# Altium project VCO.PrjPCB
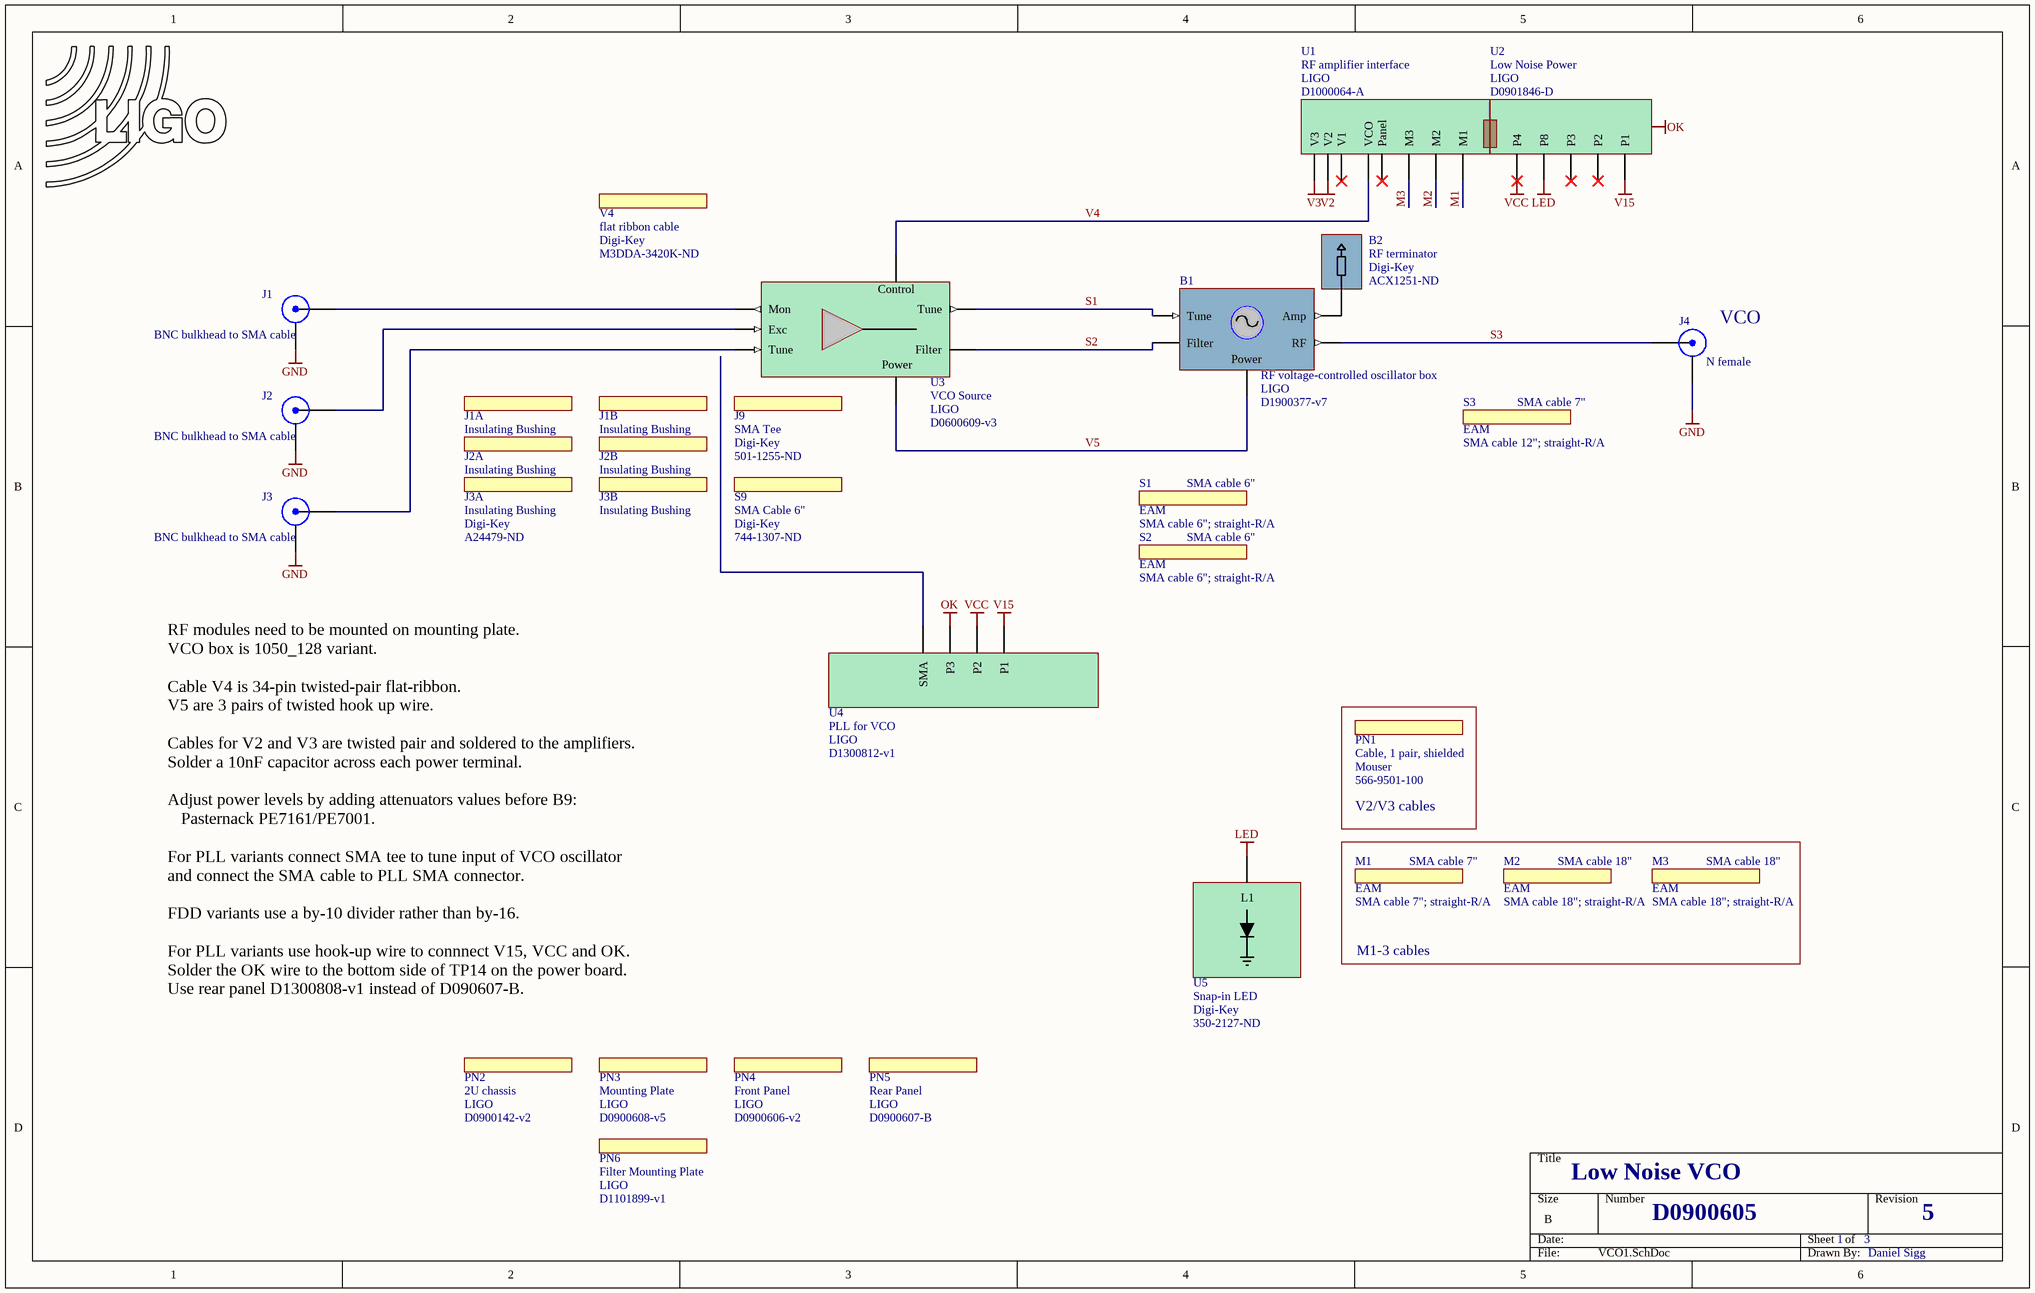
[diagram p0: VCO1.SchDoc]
Title: D0900605
3 sheets, 238 parts. Net scope: global (net labels, ports and power ports of the same name join across sheets).
Sheets:
  VCO1.SchDoc
  VCO2.SchDoc
  VCO3.SchDoc

## Sheet VCO1.SchDoc: D0900605
size B; Engineer: Daniel Sigg; Revision: 5; PageSetup: Record=PageOptions¦CenterHorizontal=True¦CenterVertical=True¦PrintScale=1.12¦XCorrection=1.00¦YCorrection=1.00¦PrintKind=0¦BorderSize=5000000¦LeftOffset=0¦BottomOffset=0¦Orientation=2¦PaperLength=1000¦PaperWidth=1000¦Scale=100¦PaperSource=7¦PrintQuality=-4¦MediaType=1¦DitherType=10¦PaperKind=11 x 17¦PrintScaleMode=1

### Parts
B1  RF voltage-controlled oscillator box  Distributor: LIGO  Part Number: D1900377-v7
B2  RF terminator  Distributor: Digi-Key  Part Number: ACX1251-ND
J1  BNC bulkhead to SMA cable  [BNC1]  (mechanical)
J1A  Insulating Bushing  (mechanical)
J1B  Insulating Bushing  (mechanical)
J2  BNC bulkhead to SMA cable  [BNC1]  (mechanical)
J2A  Insulating Bushing  (mechanical)
J2B  Insulating Bushing  (mechanical)
J3  BNC bulkhead to SMA cable  [BNC1]  (mechanical)
J3A  Insulating Bushing  Part Number: A24479-ND  Distributor: Digi-Key  (mechanical)
J3B  Insulating Bushing  (mechanical)
J4  N female  [BNC1]  (mechanical)
J9  SMA Tee  Part Number: 501-1255-ND  Distributor: Digi-Key  (mechanical)
LOGO1  LIGO logo  [LIGO_LOGO]  (value not drawn)  (no BOM)
M1  SMA cable 7"  Part Number: SMA cable 7"; straight-R/A  Distributor: EAM  (mechanical)
M2  SMA cable 18"  Part Number: SMA cable 18"; straight-R/A  Distributor: EAM  (mechanical)
M3  SMA cable 18"  Part Number: SMA cable 18"; straight-R/A  Distributor: EAM  (mechanical)
PN1  Cable, 1 pair, shielded  Part Number: 566-9501-100  Distributor: Mouser  (mechanical)
PN2  2U chassis  Part Number: D0900142-v2  Distributor: LIGO  (mechanical)
PN3  Mounting Plate  Part Number: D0900608-v5  Distributor: LIGO  (mechanical)
PN4  Front Panel  Part Number: D0900606-v2  Distributor: LIGO  (mechanical)
PN5  Rear Panel  Part Number: D0900607-B  Distributor: LIGO  (mechanical)
PN6  Filter Mounting Plate  Part Number: D1101899-v1  Distributor: LIGO  (mechanical)
S1  SMA cable 6"  Part Number: SMA cable 6"; straight-R/A  Distributor: EAM  (mechanical)
S2  SMA cable 6"  Part Number: SMA cable 6"; straight-R/A  Distributor: EAM  (mechanical)
S3  SMA cable 7"  Part Number: SMA cable 12"; straight-R/A  Distributor: EAM  (mechanical)
S9  SMA Cable 6"  Part Number: 744-1307-ND  Distributor: Digi-Key  (mechanical)
U1  RF amplifier interface  Distributor: LIGO  Part Number: D1000064-A
U2  Low Noise Power  Distributor: LIGO  Part Number: D0901846-D
U3  VCO Source  Distributor: LIGO  Part Number: D0600609-v3
U4  PLL for VCO  Distributor: LIGO  Part Number: D1300812-v1
U5  Snap-in LED  Distributor: Digi-Key  Part Number: 350-2127-ND
V4  flat ribbon cable  Part Number: M3DDA-3420K-ND  Distributor: Digi-Key  (mechanical)

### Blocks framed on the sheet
V2/V3 cables: PN1
M1-3 cables: M1-M3

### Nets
GND: J1.2(Y) J2.2(Y) J3.2(Y) J4.2(Y)
LED: U2.4(P8) U5.1(Panel)
OK: U4.3(P3)
V2: U1.6(V2)
V3: U1.7(V3)
V15: U2.1(P1) U4.1(P1)
VCC: U2.5(P4) U4.2(P2)
M1: U1.1(M1)
M2: U1.2(M2)
M3: U1.3(M3)
S1: B1.4(Tune) U3.2(Tune)
S2: B1.5(Filter) U3.1(Filter)
S3: B1.1(RF) J4.1(X)
V4: U1.8(VCO) U3.3(Power)
V5: B1.2(Power) U3.3(Power)
NetB1_3: B1.3(Amp) B2.1(I)
NetJ1_1: J1.1(X) U3.4(Mon)
NetJ2_1: J2.1(X) U3.5(Exc)
NetJ3_1: J3.1(X) U3.6(Tune)

Not connected (* = marked no-connect by the designer): U1 4(Panel)* 5(V1)*; U2 2(P2)* 3(P3)*; U4 4(SMA)

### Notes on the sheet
- (near J4) VCO
- RF modules need to be mounted on mounting plate.
  VCO box is 1050_128 variant.
  Cable V4 is 34-pin twisted-pair flat-ribbon.
  V5 are 3 pairs of twisted hook up wire.
  Cables for V2 and V3 are twisted pair and soldered to the amplifiers.
  Solder a 10nF capacitor across each power terminal.
  Adjust power levels by adding attenuators values before B9:
  Pasternack PE7161/PE7001.
  For PLL variants connect SMA tee to tune input of VCO oscillator
  and connect the SMA cable to PLL SMA connector.
  FDD variants use a by-10 divider rather than by-16.
  For PLL variants use hook-up wire to connnect V15, VCC and OK.
  Solder the OK wire to the bottom side of TP14 on the power board.
  Use rear panel D1300808-v1 instead of D090607-B.
- Low Noise VCO
- D0900605
- 1
- 3
- 5
- Daniel Sigg
- Labels drawn without touching a wire or pin: OK

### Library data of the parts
B1 = RFVCOBox
B2 = RFTerminator
J1-J3 = BNC: Part Number: PE3681-12
J1A J1B J2A J2B J3B = Partlist: Additional part number; Part Number: A24479-ND
J3A J9 PN1 PN2 PN4 PN5 S9 = Partlist: Additional part number
J4 = BNC: N-to-SMA bulkhead; Part Number: PE9252
LOGO1 = LIGO_logo
M1 S1-S3 = Partlist: Belden 1671A, L=7", SMA-SMA R/A
M2 M3 = Partlist: Belden 1671A, L=18", SMA-SMA R/A
PN3 PN6 = Partlist: panel
U1 = RFAmplifierInterface
U2 = LowNoisePower: Low Noise Power Board
U3 = RFVCOSourceV3: VCO Source V3
U4 = PLL
U5 = RFAmplifierLED: RF amplifier LED
V4 = Partlist

## Sheet VCO2.SchDoc: D0900605
size B; PageSetup: Record=PageOptions¦CenterHorizontal=True¦CenterVertical=True¦PrintScale=1.12¦XCorrection=1.00¦YCorrection=1.00¦PrintKind=0¦BorderSize=5000000¦LeftOffset=0¦BottomOffset=0¦Orientation=2¦PaperLength=1000¦PaperWidth=1000¦Scale=100¦PaperSource=7¦PrintQuality=-4¦MediaType=1¦DitherType=10¦PaperKind=11 x 17¦PrintScaleMode=1
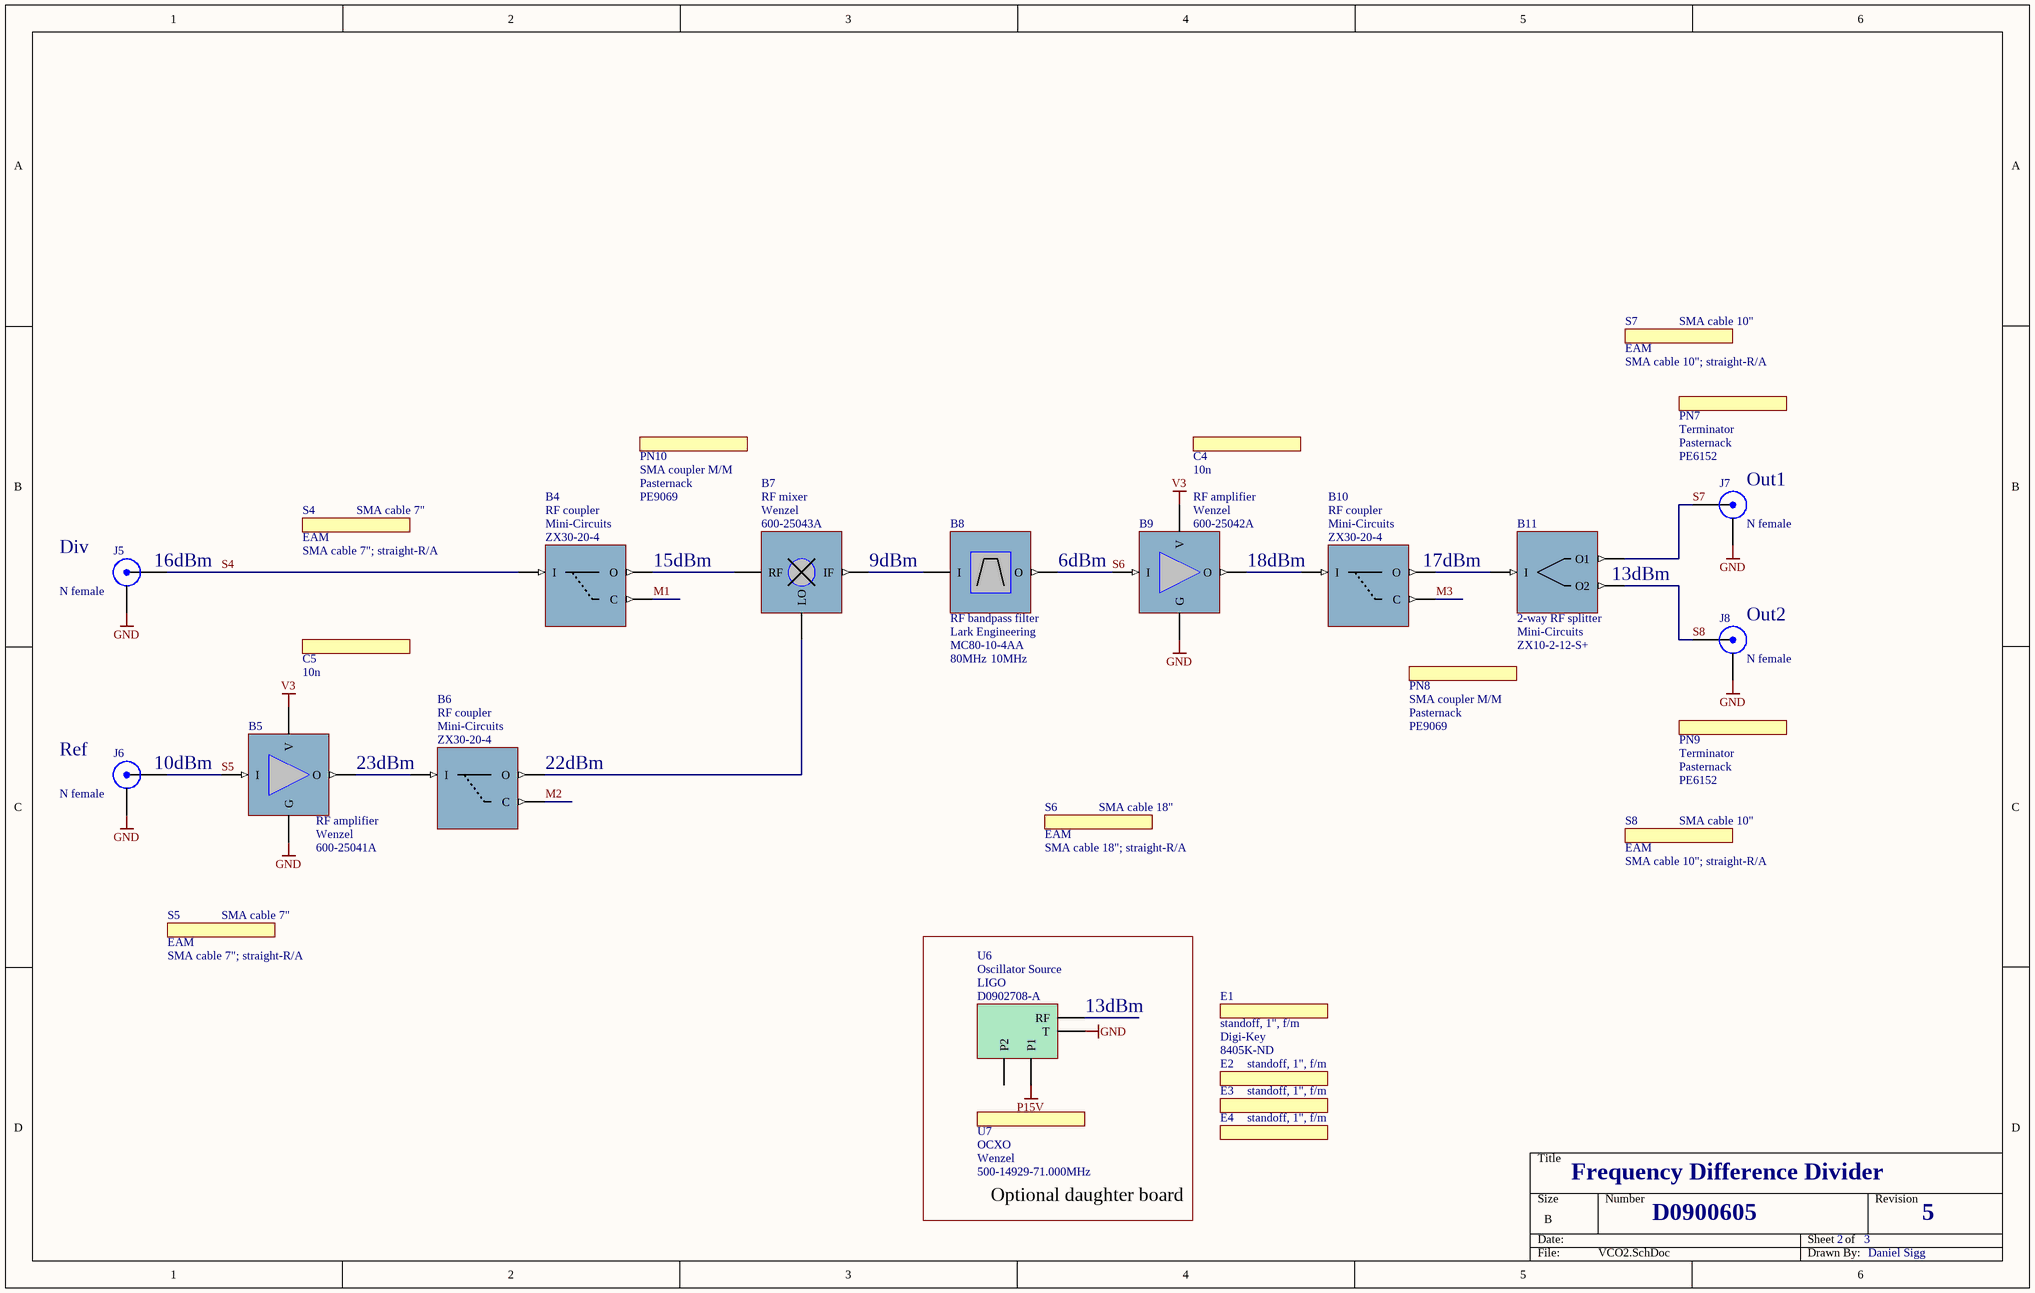
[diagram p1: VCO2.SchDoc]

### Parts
B4  RF coupler  Distributor: Mini-Circuits  Part Number: ZX30-20-4  (mechanical)
B5  RF amplifier  Distributor: Wenzel  Part Number: 600-25041A  (mechanical)
B6  RF coupler  Distributor: Mini-Circuits  Part Number: ZX30-20-4  (mechanical)
B7  RF mixer  Distributor: Wenzel  Part Number: 600-25043A  (mechanical)
B8  RF bandpass filter  Distributor: Lark Engineering  Part Number: MC80-10-4AA  Center Frequency: 80MHz  Width: 10MHz  (mechanical)
B9  RF amplifier  Distributor: Wenzel  Part Number: 600-25042A  (mechanical)
B10  RF coupler  Distributor: Mini-Circuits  Part Number: ZX30-20-4  (mechanical)
B11  2-way RF splitter  Distributor: Mini-Circuits  Part Number: ZX10-2-12-S+  (mechanical)
C4  10n  (mechanical)
C5  10n  (mechanical)
E1  standoff, 1", f/m  Part Number: 8405K-ND  Distributor: Digi-Key  (mechanical)
E2  standoff, 1", f/m  (mechanical)
E3  standoff, 1", f/m  (mechanical)
E4  standoff, 1", f/m  (mechanical)
J5  N female  [BNC1]  (mechanical)
J6  N female  [BNC1]  (mechanical)
J7  N female  [BNC1]  (mechanical)
J8  N female  [BNC1]  (mechanical)
PN7  Terminator  Part Number: PE6152  Distributor: Pasternack  (mechanical)
PN8  SMA coupler M/M  Part Number: PE9069  Distributor: Pasternack  (mechanical)
PN9  Terminator  Part Number: PE6152  Distributor: Pasternack  (mechanical)
PN10  SMA coupler M/M  Part Number: PE9069  Distributor: Pasternack  (mechanical)
S4  SMA cable 7"  Part Number: SMA cable 7"; straight-R/A  Distributor: EAM  (mechanical)
S5  SMA cable 7"  Part Number: SMA cable 7"; straight-R/A  Distributor: EAM  (mechanical)
S6  SMA cable 18"  Part Number: SMA cable 18"; straight-R/A  Distributor: EAM  (mechanical)
S7  SMA cable 10"  Part Number: SMA cable 10"; straight-R/A  Distributor: EAM  (mechanical)
S8  SMA cable 10"  Part Number: SMA cable 10"; straight-R/A  Distributor: EAM  (mechanical)
U6  Oscillator Source  Distributor: LIGO  Part Number: D0902708-A  (no BOM)
U7  OCXO  Part Number: 500-14929-71.000MHz  Distributor: Wenzel  (no BOM)

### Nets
GND: B5.3(G) B9.3(G) J5.2(Y) J6.2(Y) J7.2(Y) J8.2(Y) U6.4(T)
P15V: U6.1(P1)
V3: B5.2(V) B9.2(V)
M1: B4.2(C)
M2: B6.2(C)
M3: B10.2(C)
S4: B4.0(I) J5.1(X)
S5: B5.0(I) J6.1(X)
S6: B8.2(O) B9.0(I)
S7: B11.1(O1) J7.1(X)
S8: B11.2(O2) J8.1(X)
NetB4_1: B4.1(O) B7.3(RF)
NetB5_1: B5.1(O) B6.0(I)
NetB6_1: B6.1(O) B7.2(LO)
NetB7_1: B7.1(IF) B8.1(I)
NetB9_1: B9.1(O) B10.0(I)
NetB10_1: B10.1(O) B11.0(I)

Not connected (* = marked no-connect by the designer): U6 2(P2) 3(RF)

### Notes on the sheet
- (near J7) Out1
- (near J5) Div
- (near J5) 16dBm
- (near B4) 15dBm
- 9dBm
- 6dBm
- 18dBm
- (near B10) 17dBm
- (near B11) 13dBm
- (near J8) Out2
- (near J6) Ref
- (near J6) 10dBm
- 23dBm
- (near B6) 22dBm
- (near U6) 13dBm
- Frequency Difference Divider
- Optional daughter board
- D0900605
- 2
- 3
- 5
- Daniel Sigg

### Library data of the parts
B4 B6 B10 = RFCoupler
B5 B9 = RFAmplifier
B7 = RFMixer
B8 = RFBandpass
B11 = RFSplitter2
C4 C5 = Partlist: Capacitor; Part Number: 445-4750-ND
E1 PN7 PN9 = Partlist
E2-E4 = Partlist: Part Number: 8405K-ND
J5-J8 = BNC: N-to-SMA bulkhead; Part Number: PE9252
PN8 PN10 = Partlist: Terminator
S4 S5 = Partlist: Belden 1671A, L=7", SMA-SMA R/A
S6 = Partlist: Belden 1671A, L=18", SMA-SMA R/A
S7 S8 = Partlist: Belden 1671A, L=10", SMA-SMA R/A
U6 = SqueezerOscillator: Squeezer Oscillator Source
U7 = Partlist: RF oscillator

## Sheet VCO3.SchDoc: D0900605
size B
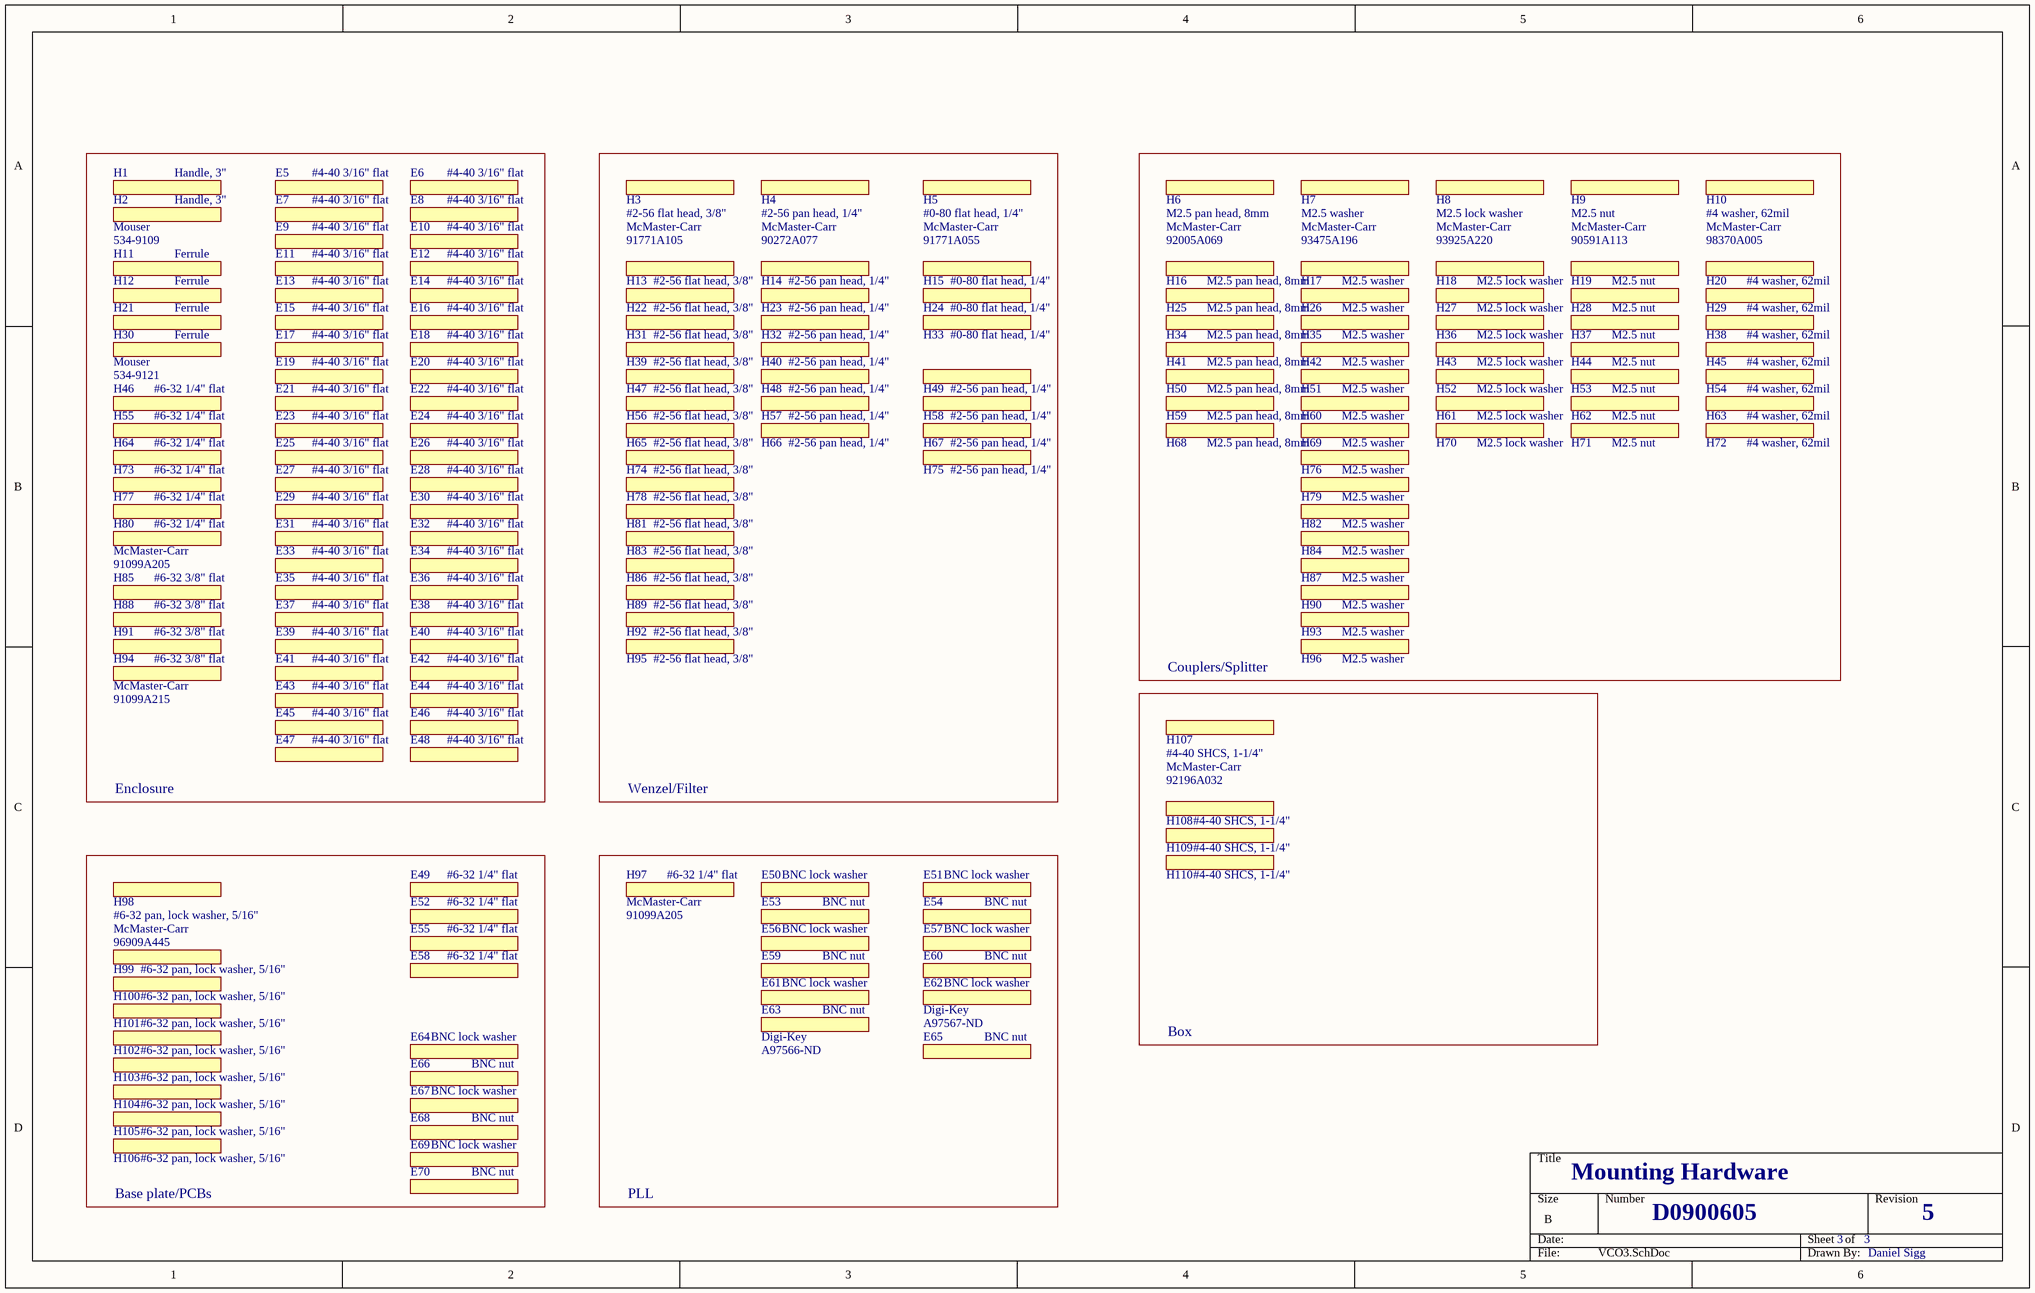
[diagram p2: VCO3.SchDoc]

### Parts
E5  #4-40 3/16" flat  (mechanical)
E6  #4-40 3/16" flat  (mechanical)
E7  #4-40 3/16" flat  (mechanical)
E8  #4-40 3/16" flat  (mechanical)
E9  #4-40 3/16" flat  (mechanical)
E10  #4-40 3/16" flat  (mechanical)
E11  #4-40 3/16" flat  (mechanical)
E12  #4-40 3/16" flat  (mechanical)
E13  #4-40 3/16" flat  (mechanical)
E14  #4-40 3/16" flat  (mechanical)
E15  #4-40 3/16" flat  (mechanical)
E16  #4-40 3/16" flat  (mechanical)
E17  #4-40 3/16" flat  (mechanical)
E18  #4-40 3/16" flat  (mechanical)
E19  #4-40 3/16" flat  (mechanical)
E20  #4-40 3/16" flat  (mechanical)
E21  #4-40 3/16" flat  (mechanical)
E22  #4-40 3/16" flat  (mechanical)
E23  #4-40 3/16" flat  (mechanical)
E24  #4-40 3/16" flat  (mechanical)
E25  #4-40 3/16" flat  (mechanical)
E26  #4-40 3/16" flat  (mechanical)
E27  #4-40 3/16" flat  (mechanical)
E28  #4-40 3/16" flat  (mechanical)
E29  #4-40 3/16" flat  (mechanical)
E30  #4-40 3/16" flat  (mechanical)
E31  #4-40 3/16" flat  (mechanical)
E32  #4-40 3/16" flat  (mechanical)
E33  #4-40 3/16" flat  (mechanical)
E34  #4-40 3/16" flat  (mechanical)
E35  #4-40 3/16" flat  (mechanical)
E36  #4-40 3/16" flat  (mechanical)
E37  #4-40 3/16" flat  (mechanical)
E38  #4-40 3/16" flat  (mechanical)
E39  #4-40 3/16" flat  (mechanical)
E40  #4-40 3/16" flat  (mechanical)
E41  #4-40 3/16" flat  (mechanical)
E42  #4-40 3/16" flat  (mechanical)
E43  #4-40 3/16" flat  (mechanical)
E44  #4-40 3/16" flat  (mechanical)
E45  #4-40 3/16" flat  (mechanical)
E46  #4-40 3/16" flat  (mechanical)
E47  #4-40 3/16" flat  (mechanical)
E48  #4-40 3/16" flat  (mechanical)
E49  #6-32 1/4" flat  (mechanical)
E50  BNC lock washer  (mechanical)
E51  BNC lock washer  (mechanical)
E52  #6-32 1/4" flat  (mechanical)
E53  BNC nut  (mechanical)
E54  BNC nut  (mechanical)
E55  #6-32 1/4" flat  (mechanical)
E56  BNC lock washer  (mechanical)
E57  BNC lock washer  (mechanical)
E58  #6-32 1/4" flat  (mechanical)
E59  BNC nut  (mechanical)
E60  BNC nut  (mechanical)
E61  BNC lock washer  (mechanical)
E62  BNC lock washer  Part Number: A97567-ND  Distributor: Digi-Key  (mechanical)
E63  BNC nut  Part Number: A97566-ND  Distributor: Digi-Key  (mechanical)
E64  BNC lock washer  (mechanical)
E65  BNC nut  (mechanical)
E66  BNC nut  (mechanical)
E67  BNC lock washer  (mechanical)
E68  BNC nut  (mechanical)
E69  BNC lock washer  (mechanical)
E70  BNC nut  (mechanical)
H1  Handle, 3"  (mechanical)
H2  Handle, 3"  Part Number: 534-9109  Distributor: Mouser  (mechanical)
H3  #2-56 flat head, 3/8"  Part Number: 91771A105  Distributor: McMaster-Carr  (mechanical)
H4  #2-56 pan head, 1/4"  Part Number: 90272A077  Distributor: McMaster-Carr  (mechanical)
H5  #0-80 flat head, 1/4"  Part Number: 91771A055  Distributor: McMaster-Carr  (mechanical)
H6  M2.5 pan head, 8mm  Part Number: 92005A069  Distributor: McMaster-Carr  (mechanical)
H7  M2.5 washer  Part Number: 93475A196  Distributor: McMaster-Carr  (mechanical)
H8  M2.5 lock washer  Part Number: 93925A220  Distributor: McMaster-Carr  (mechanical)
H9  M2.5 nut  Part Number: 90591A113  Distributor: McMaster-Carr  (mechanical)
H10  #4 washer, 62mil  Part Number: 98370A005  Distributor: McMaster-Carr  (mechanical)
H11  Ferrule  (mechanical)
H12  Ferrule  (mechanical)
H13  #2-56 flat head, 3/8"  (mechanical)
H14  #2-56 pan head, 1/4"  (mechanical)
H15  #0-80 flat head, 1/4"  (mechanical)
H16  M2.5 pan head, 8mm  (mechanical)
H17  M2.5 washer  (mechanical)
H18  M2.5 lock washer  (mechanical)
H19  M2.5 nut  (mechanical)
H20  #4 washer, 62mil  (mechanical)
H21  Ferrule  (mechanical)
H22  #2-56 flat head, 3/8"  (mechanical)
H23  #2-56 pan head, 1/4"  (mechanical)
H24  #0-80 flat head, 1/4"  (mechanical)
H25  M2.5 pan head, 8mm  (mechanical)
H26  M2.5 washer  (mechanical)
H27  M2.5 lock washer  (mechanical)
H28  M2.5 nut  (mechanical)
H29  #4 washer, 62mil  (mechanical)
H30  Ferrule  Part Number: 534-9121  Distributor: Mouser  (mechanical)
H31  #2-56 flat head, 3/8"  (mechanical)
H32  #2-56 pan head, 1/4"  (mechanical)
H33  #0-80 flat head, 1/4"  (mechanical)
H34  M2.5 pan head, 8mm  (mechanical)
H35  M2.5 washer  (mechanical)
H36  M2.5 lock washer  (mechanical)
H37  M2.5 nut  (mechanical)
H38  #4 washer, 62mil  (mechanical)
H39  #2-56 flat head, 3/8"  (mechanical)
H40  #2-56 pan head, 1/4"  (mechanical)
H41  M2.5 pan head, 8mm  (mechanical)
H42  M2.5 washer  (mechanical)
H43  M2.5 lock washer  (mechanical)
H44  M2.5 nut  (mechanical)
H45  #4 washer, 62mil  (mechanical)
H46  #6-32 1/4" flat  (mechanical)
H47  #2-56 flat head, 3/8"  (mechanical)
H48  #2-56 pan head, 1/4"  (mechanical)
H49  #2-56 pan head, 1/4"  (mechanical)
H50  M2.5 pan head, 8mm  (mechanical)
H51  M2.5 washer  (mechanical)
H52  M2.5 lock washer  (mechanical)
H53  M2.5 nut  (mechanical)
H54  #4 washer, 62mil  (mechanical)
H55  #6-32 1/4" flat  (mechanical)
H56  #2-56 flat head, 3/8"  (mechanical)
H57  #2-56 pan head, 1/4"  (mechanical)
H58  #2-56 pan head, 1/4"  (mechanical)
H59  M2.5 pan head, 8mm  (mechanical)
H60  M2.5 washer  (mechanical)
H61  M2.5 lock washer  (mechanical)
H62  M2.5 nut  (mechanical)
H63  #4 washer, 62mil  (mechanical)
H64  #6-32 1/4" flat  (mechanical)
H65  #2-56 flat head, 3/8"  (mechanical)
H66  #2-56 pan head, 1/4"  (mechanical)
H67  #2-56 pan head, 1/4"  (mechanical)
H68  M2.5 pan head, 8mm  (mechanical)
H69  M2.5 washer  (mechanical)
H70  M2.5 lock washer  (mechanical)
H71  M2.5 nut  (mechanical)
H72  #4 washer, 62mil  (mechanical)
H73  #6-32 1/4" flat  (mechanical)
H74  #2-56 flat head, 3/8"  (mechanical)
H75  #2-56 pan head, 1/4"  (mechanical)
H76  M2.5 washer  (mechanical)
H77  #6-32 1/4" flat  (mechanical)
H78  #2-56 flat head, 3/8"  (mechanical)
H79  M2.5 washer  (mechanical)
H80  #6-32 1/4" flat  Part Number: 91099A205  Distributor: McMaster-Carr  (mechanical)
H81  #2-56 flat head, 3/8"  (mechanical)
H82  M2.5 washer  (mechanical)
H83  #2-56 flat head, 3/8"  (mechanical)
H84  M2.5 washer  (mechanical)
H85  #6-32 3/8" flat  (mechanical)
H86  #2-56 flat head, 3/8"  (mechanical)
H87  M2.5 washer  (mechanical)
H88  #6-32 3/8" flat  (mechanical)
H89  #2-56 flat head, 3/8"  (mechanical)
H90  M2.5 washer  (mechanical)
H91  #6-32 3/8" flat  (mechanical)
H92  #2-56 flat head, 3/8"  (mechanical)
H93  M2.5 washer  (mechanical)
H94  #6-32 3/8" flat  Part Number: 91099A215  Distributor: McMaster-Carr  (mechanical)
H95  #2-56 flat head, 3/8"  (mechanical)
H96  M2.5 washer  (mechanical)
H97  #6-32 1/4" flat  Part Number: 91099A205  Distributor: McMaster-Carr  (mechanical)
H98  #6-32 pan, lock washer, 5/16"  Part Number: 96909A445  Distributor: McMaster-Carr  (mechanical)
H99  #6-32 pan, lock washer, 5/16"  (mechanical)
H100  #6-32 pan, lock washer, 5/16"  (mechanical)
H101  #6-32 pan, lock washer, 5/16"  (mechanical)
H102  #6-32 pan, lock washer, 5/16"  (mechanical)
H103  #6-32 pan, lock washer, 5/16"  (mechanical)
H104  #6-32 pan, lock washer, 5/16"  (mechanical)
H105  #6-32 pan, lock washer, 5/16"  (mechanical)
H106  #6-32 pan, lock washer, 5/16"  (mechanical)
H107  #4-40 SHCS, 1-1/4"  Part Number: 92196A032  Distributor: McMaster-Carr  (mechanical)
H108  #4-40 SHCS, 1-1/4"  (mechanical)
H109  #4-40 SHCS, 1-1/4"  (mechanical)
H110  #4-40 SHCS, 1-1/4"  (mechanical)

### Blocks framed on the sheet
Enclosure: E5-E48 H1 H2 H11 H12 H21 H30 H46 H55 H64 H73 H77 H80 H85 H88 H91 H94
Wenzel/Filter: H3-H5 H13-H15 H22-H24 H31-H33 H39 H40 H47-H49 H56-H58 H65-H67 H74 H75 H78 H81 H83 H86 H89 H92 H95
Couplers/Splitter: H6-H10 H16-H20 H25-H29 H34-H38 H41-H45 H50-H54 H59-H63 H68-H72 H76 H79 H82 H84 H87 H90 H93 H96
Base plate/PCBs: E49 E52 E55 E58 E64 E66-E70 H98-H106
PLL: E50 E51 E53 E54 E56 E57 E59-E63 E65 H97

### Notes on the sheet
- Box
- Mounting Hardware
- D0900605
- 3
- 5
- Daniel Sigg

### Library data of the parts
E5-E48 = Partlist: #4-40 3/16" flat head screw; Part Number: 91771A111
E49 E52 E55 E58 H46 H55 H64 H73 H77 = Partlist: #6-32 1/4" flat head screw; Part Number: 91099A205
E50 E51 E56 E57 E61 E64 E67 E69 = Partlist: Part Number: A97567-ND
E53 E54 E59 E60 E65 E66 E68 E70 = Partlist: Part Number: A97566-ND
E62 E63 H7 H8 H30 = Partlist
H1 = Partlist: Rack handle 2U; Part Number: 534-9109
H2 = Partlist: Rack handle 2U
H3 = Partlist: #2-56 flat head screw, 3/8"
H4 H107 = Partlist: #2-56 pan head screw, 1/4"
H5 = Partlist: #0-80 flat head screw, 1/4"
H6 = Partlist: M2.5 pan head screw, 8mm
H9 = Partlist: M2.5 hex nut
H10 = Partlist: #4 washer, 62mil thick
H11 H12 H21 = Partlist: Part Number: 534-9121
H13 H22 H31 H39 H47 H56 H65 H74 H78 H81 H83 H86 H89 H92 H95 = Partlist: #2-56 flat head screw, 3/8"; Part Number: 91771A105
H14 H23 H32 H40 H48 H49 H57 H58 H66 H67 H75 = Partlist: #2-56 pan head screw, 1/4"; Part Number: 90272A077
H15 H24 H33 = Partlist: #0-80 flat head screw, 1/4"; Part Number: 91771A055
H16 H25 H34 H41 H50 H59 H68 = Partlist: M2.5 pan head screw, 8mm; Part Number: 92005A069
H17 H26 H35 H42 H51 H60 H69 H76 H79 H82 H84 H87 H90 H93 H96 = Partlist: Part Number: 93475A196
H18 H27 H36 H43 H52 H61 H70 = Partlist: Part Number: 93925A220
H19 H28 H37 H44 H53 H62 H71 = Partlist: M2.5 hex nut; Part Number: 90591A113
H20 H29 H38 H45 H54 H63 H72 = Partlist: #4 washer, 62mil thick; Part Number: 98370A005
H80 H97 = Partlist: #6-32 1/4" flat head screw
H85 H88 H91 = Partlist: #6-32 3/8" flat head screw; Part Number: 91099A215
H94 = Partlist: #6-32 3/8" flat head screw
H98 = Partlist: #6-32 pan head screw with lock washer, 5/16"
H99-H106 = Partlist: #6-32 pan head screw with lock washer, 5/16"; Part Number: 96909A445
H108-H110 = Partlist: #2-56 pan head screw, 1/4"; Part Number: 92196A032

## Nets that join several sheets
GND: VCO1 (J1.2 J2.2 J3.2 J4.2), VCO2 (7 pins)
V3: VCO1 (U1.7), VCO2 (B5.2 B9.2)
M1: VCO1 (U1.1), VCO2 (B4.2)
M2: VCO1 (U1.2), VCO2 (B6.2)
M3: VCO1 (U1.3), VCO2 (B10.2)

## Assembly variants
Standard: not fitted E53 E53 E54 E54 E55 E55 E56 E56 E57 E57 E58 E58 H? J? J? U?
FDD: not fitted E53 E53 E54 E54 E55 E55 E56 E56 E57 E57 E58 E58 H? J? J? U?
PLL: all parts fitted
FDD/PLL: all parts fitted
